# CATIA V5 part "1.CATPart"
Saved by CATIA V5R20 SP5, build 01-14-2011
Part number: 创意
Material "Aluminium": density 2710 kg/m3, Young's modulus 7e+10 Pa, Poisson ratio 0.346, thermal expansion 2.36e-05 1/K
Bounding box of the stored display mesh (mm): x -39 to 39, y -81 to 114.612, z -3.99 to 5.5
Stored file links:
  E:\scc\chuangyi.CATPart
  C:\Program Files\Dassault Systemes\B20\intel_a\startup\materials\Catalog.CATMaterial
  C:\Program Files\Dassault Systemes\B20\intel_a\startup\materials\lead.jpg
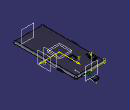
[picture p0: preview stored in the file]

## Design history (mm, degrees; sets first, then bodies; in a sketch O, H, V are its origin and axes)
Body1 (main body), material "Aluminium"
  Sketch1 on xy-plane, origin (0, 0, 0), H (1, 0, 0), V (0, 1, 0)
    line L1 (38.5, 81) -> (38.5, -81)
    line L2 (38.5, -81) -> (-38.5, -81)
    line L3 (-38.5, -81) -> (-38.5, 81)
    line L4 (-38.5, 81) -> (38.5, 81)
    length L4 = 77
    length L1 = 162
    vertical: L1 V, L3 V
    horizontal: L2 H, L4 H
    equidistance: L1 L3 O, L2 L4 O
  Pad1: profile Sketch1, direction (0, 0, 1), length 3.99, mirrored extent
  Fillet1: radius 5, on edge [face of Pad1 from Sketch1.L2 | face of Pad1 from Sketch1.L3]
  Fillet2: radius 5, on edge [face of Pad1 from Sketch1.L1 | face of Pad1 from Sketch1.L2]; edge [face of Pad1 from Sketch1.L4 | face of Pad1 from Sketch1.L1]; edge [face of Pad1 from Sketch1.L3 | face of Pad1 from Sketch1.L4]
  Fillet3: radius 3.99, on edge [face of Pad1 from Sketch1.L3 | end face of Pad1]
  Fillet4: radius 3.99, on edge [start face of Pad1 | face of Pad1 from Sketch1.L3]
  Sketch2 on xy-plane, origin (0, 0, 0), H (1, 0, 0), V (0, 1, 0)
    point P1 (0, 36.3564)
    line L1 (6, 42.3564) -> (6, 30.3564)
    line L2 (6, 30.3564) -> (-6, 30.3564)
    line L3 (-6, 30.3564) -> (-6, 42.3564)
    line L4 (-6, 42.3564) -> (6, 42.3564)
    construction line L5 (-25.3865, 65.2808) -> (-25.3865, 54.4342)
    line L6 (-20.2504, 65.2808) -> (-20.2504, 54.4342)
    line L7 (-30.5227, 54.4342) -> (-30.5227, 65.2808)
    arc A1 centre (-25.3865, 54.4342) radius 5.1361 from (-20.2504, 54.4342) to (-30.5227, 54.4342) cw
    arc A2 centre (-25.3865, 65.2808) radius 5.1361 from (-30.5227, 65.2808) to (-20.2504, 65.2808) cw
    circle A3 centre (-25.3865, 43.9892) radius 1.6328
    point P12 (-25.3865, 43.9892)
    point P13 (-25.3865, 45.6221)
    circle A4 centre (-25.3865, 65.2808) radius 2.0148
    circle A5 centre (-25.3865, 65.2808) radius 3.1825
    circle A6 centre (-25.3865, 54.4342) radius 1.4225
    circle A7 centre (-25.3865, 54.4342) radius 2.9911
    length L1 = 12
    length L2 = 12
    distance L5 L6 = 5.1361
    coincidence: P1 V, P12 L5, A3 P13, P13 L5
    vertical: L1 V, L3 V, L5 V
    horizontal: L2 H, L4 H
    equidistance: L1 L3 P1, L2 L4 P1
    tangency: A1 L6, A2 L6, A1 L7, A2 L7, A3 L4
  Pocket1: profile Sketch2, direction (0, 0, -1), length 1
  Sketch3 on xy-plane, origin (0, 0, 0), H (1, 0, 0), V (0, 1, 0)
    construction line L1 (-25.4108, 65.0293) -> (-25.4108, 53.2602)
    line L2 (-19.9486, 65.0293) -> (-19.9486, 53.2602)
    line L3 (-30.8731, 53.2602) -> (-30.8731, 65.0293)
    arc A1 centre (-25.4108, 53.2602) radius 5.4623 from (-19.9486, 53.2602) to (-30.8731, 53.2602) cw
    arc A2 centre (-25.4108, 65.0293) radius 5.4623 from (-30.8731, 65.0293) to (-19.9486, 65.0293) cw
    circle A3 centre (-25.4108, 65.0293) radius 1.7194
    circle A4 centre (-25.4108, 65.0293) radius 3.6037
    circle A5 centre (-25.4108, 53.2602) radius 1.997
    circle A6 centre (-25.4108, 53.2602) radius 3.278
    distance L1 L2 = 5.4623
    vertical: L1 V
    tangency: A1 L2, A2 L2, A1 L3, A2 L3
  Pad2: profile Sketch3, direction (0, 0, 1), length 1
  Sketch4 on xy-plane, origin (0, 0, 0), H (1, 0, 0), V (0, 1, 0)
    construction line L1 (-24.8106, 64.61) -> (-24.8106, 53.11)
    point P1 (-24.8106, 64.61)
    line L2 (-19.1177, 64.61) -> (-19.1177, 53.11)
    line L3 (-30.5034, 53.11) -> (-30.5034, 64.61)
    arc A1 centre (-24.8106, 53.11) radius 5.6928 from (-19.1177, 53.11) to (-30.5034, 53.11) cw
    arc A2 centre (-24.8106, 64.61) radius 5.6928 from (-30.5034, 64.61) to (-19.1177, 64.61) cw
    reference projected line E1 (-33.5, 77.01) -> (33.5, 77.01) from edge [end face of Pad1 | face of Fillet3]
    distance L1 L2 = 5.6928
    length L2 = 11.5
    distance P1 E1 = 12.4
    vertical: L1 V
    tangency: A1 L2, A2 L2, A1 L3, A2 L3
  Sketch5 on xy-plane, origin (0, 0, 0), H (1, 0, 0), V (0, 1, 0)
    construction line L1 (-24.8106, 64.8298) -> (-24.8106, 53.0607)
    point P1 (-24.8106, 64.8298)
    line L2 (-19.6083, 64.8298) -> (-19.6083, 53.0607)
    line L3 (-30.0128, 53.0607) -> (-30.0128, 64.8298)
    arc A1 centre (-24.8106, 53.0607) radius 5.2023 from (-19.6083, 53.0607) to (-30.0128, 53.0607) cw
    arc A2 centre (-24.8106, 64.8298) radius 5.2023 from (-30.0128, 64.8298) to (-19.6083, 64.8298) cw
    reference projected line E1 (-33.5, 77.01) -> (33.5, 77.01) from edge [end face of Pad1 | face of Fillet3]
    reference projected line E2 (-34.51, -76) -> (-34.51, 76) from edge [end face of Pad1 | face of Fillet3]
    distance L1 L2 = 5.2023
    length L2 = 11.7691
    distance E1 P1 = 12.1802
    distance E2 L3 = 4.4972
    vertical: L1 V
    tangency: A1 L2, A2 L2, A1 L3, A2 L3
  Pad3: profile Sketch4, direction (0, 0, 1), length 1
  Pad4: profile Sketch5, direction (0, 0, 1), length 1
  Sketch6 on xy-plane, origin (0, 0, 0), H (1, 0, 0), V (0, 1, 0)
    construction line L1 (-25.2798, 64.8632) -> (-25.2798, 53.3363)
    point P2 (-25.2798, 53.3363)
    line L2 (-19.9502, 64.8632) -> (-19.9502, 53.3363)
    line L3 (-30.6093, 53.3363) -> (-30.6093, 64.8632)
    arc A1 centre (-25.2798, 53.3363) radius 5.3295 from (-19.9502, 53.3363) to (-30.6093, 53.3363) cw
    arc A2 centre (-25.2798, 64.8632) radius 5.3295 from (-30.6093, 64.8632) to (-19.9502, 64.8632) cw
    distance L1 L2 = 5.3295
    distance H P2 = 53.3363
    length L2 = 11.5269
    vertical: L1 V
    tangency: A1 L2, A2 L2, A1 L3, A2 L3
  Pad5: profile Sketch6, direction (0, 0, 1), length 3
  Sketch7 on xy-plane, origin (0, 0, 0), H (1, 0, 0), V (0, 1, 0)
    construction line L1 (-25.4757, 64.8633) -> (-25.4757, 53.9225)
    point P2 (-25.4757, 53.9225)
    line L2 (-20.3384, 64.8633) -> (-20.3384, 53.9225)
    line L3 (-30.6131, 53.9225) -> (-30.6131, 64.8633)
    arc A1 centre (-25.4757, 53.9225) radius 5.1374 from (-20.3384, 53.9225) to (-30.6131, 53.9225) cw
    arc A2 centre (-25.4757, 64.8633) radius 5.1374 from (-30.6131, 64.8633) to (-20.3384, 64.8633) cw
    distance L1 L2 = 5.1374
    distance P2 H = 53.9225
    length L2 = 10.9408
    vertical: L1 V
    tangency: A1 L2, A2 L2, A1 L3, A2 L3
  Pad6: profile Sketch7, direction (0, 0, 1), length 4.99
  Sketch8 on xy-plane, origin (0, 0, 0), H (1, 0, 0), V (0, 1, 0)
    circle A1 centre (-25.2798, 65.0586) radius 1.4118
    circle A2 centre (-25.2798, 65.0586) radius 2.7436
    circle A3 centre (-25.2798, 54.1178) radius 1.2533
    circle A4 centre (-25.2798, 54.1178) radius 2.9395
    radius A1 = 1.4118
    radius A2 = 2.7436
    radius A3 = 1.2533
    radius A4 = 2.9395
  Pad7: profile Sketch8, direction (0, 0, 1), length 5.5
  Sketch9 on xy-plane, origin (0, 0, 0), H (1, 0, 0), V (0, 1, 0)
    circle A1 centre (-25.3429, 44.3174) radius 1.1965
    circle A2 centre (-25.3429, 44.3174) radius 2.198
    radius A1 = 1.1965
    radius A2 = 2.198
  Pad8: profile Sketch9, direction (0, 0, 1), length 4
  Plane1: type Offset, RefPlane xy-plane, Offset 3.99
  Sketch10 on Plane1, origin (0, 0, 3.99), H (1, 0, 0), V (0, 1, 0)
    point P1 (0, 33.0703)
    line L1 (6, 39.0703) -> (6, 27.0703)
    line L2 (6, 27.0703) -> (-6, 27.0703)
    line L3 (-6, 27.0703) -> (-6, 39.0703)
    line L4 (-6, 39.0703) -> (6, 39.0703)
    length L1 = 12
    length L2 = 12
    coincidence: P1 V
    vertical: L1 V, L3 V
    horizontal: L2 H, L4 H
    equidistance: L1 L3 P1, L2 L4 P1
  Pocket2: profile Sketch10, direction (0, 0, -1), length 1
  Fillet5: radius 0.5, on edge [end face of Pad1 | face of Pocket2 from Sketch10.L4]; edge [end face of Pad1 | face of Pocket2 from Sketch10.L1]
  Fillet6: radius 0.5, on edge [end face of Pad1 | face of Pocket2 from Sketch10.L2]
  Fillet7: radius 0.5, on edge [end face of Pad1 | face of Pocket2 from Sketch10.L3]
  Fillet8: radius 0.5, on edge [face of Fillet5 | face of Fillet7]
  Sketch11 on zx-plane, origin (0, 0, 0), H (-1, 0, 0), V (0, 0, 1)
    point P1 (-21.6197, 0)
    line L1 (-16.608, 1.3345) -> (-16.608, -1.3345)
    line L2 (-16.608, -1.3345) -> (-26.6314, -1.3345)
    line L3 (-26.6314, -1.3345) -> (-26.6314, 1.3345)
    line L4 (-26.6314, 1.3345) -> (-16.608, 1.3345)
    length L4 = 10.0234
    length L1 = 2.669
    coincidence: P1 H
    vertical: L1 V, L3 V
    horizontal: L2 H, L4 H
    equidistance: L1 L3 P1, L2 L4 P1
  Pad9: profile Sketch11, direction (0, 1, 0), length 1
  Plane2: type Offset, RefPlane zx-plane, Offset 81
  Sketch12 on Plane2, origin (0, 81, 0), H (-1, 0, 0), V (0, 0, 1)
    circle A1 centre (7.2071, 0) radius 0.3459
    point P1 (7.2071, 0)
    point P2 (7.5531, 0)
    circle A2 centre (15.1062, 0) radius 1.1562
    point P3 (15.1062, 0)
    coincidence: P1 H, A1 P2, P2 H, P3 H
  Pocket3: profile Sketch12, direction (0, -1, 0), length 5
  Plane3: type Offset, RefPlane yz-plane, Offset 38.5
  Sketch13 on Plane3, origin (38.5, 0, 0), H (0, 1, 0), V (0, 0, 1)
    construction line L1 (31.5997, 0) -> (47.6279, 0)
    point P1 (31.5997, 0)
    point P2 (47.6279, 0)
    line L2 (31.5997, 1.8741) -> (47.6279, 1.8741)
    line L3 (47.6279, -1.8741) -> (31.5997, -1.8741)
    arc A1 centre (47.6279, 0) radius 1.8741 from (47.6279, 1.8741) to (47.6279, -1.8741) cw
    arc A2 centre (31.5997, 0) radius 1.8741 from (31.5997, -1.8741) to (31.5997, 1.8741) cw
    reference intersected line E1 through (81, 0) direction (0, 1) from Plane2
    distance L1 L2 = 1.8741
    length L3 = 16.0282
    distance P2 E1 = 33.3721
    coincidence: P1 H
    horizontal: L1 H
    tangency: A1 L2, A2 L2, A1 L3, A2 L3
  Pad10: profile Sketch13, direction (1, 0, 0), length 0.5
  Sketch14 on Plane3, origin (38.5, 0, 0), H (0, 1, 0), V (0, 0, 1)
    point P1 (11.3902, 0)
    line L1 (18.359, 1.3919) -> (18.359, -1.3919)
    line L2 (18.359, -1.3919) -> (4.4214, -1.3919)
    line L3 (4.4214, -1.3919) -> (4.4214, 1.3919)
    line L4 (4.4214, 1.3919) -> (18.359, 1.3919)
    length L2 = 13.9376
    coincidence: P1 H
    vertical: L1 V, L3 V
    horizontal: L2 H, L4 H
    equidistance: L1 L3 P1, L2 L4 P1
  Pad11: profile Sketch14, direction (1, 0, 0), length 0.5
  Sketch15 on yz-plane, origin (0, 0, 0), H (0, 1, 0), V (0, 0, 1)
    line L1 (8.1368, 1.5106) -> (8.1368, -1.5106)
    line L2 (8.1368, -1.5106) -> (-8.1368, -1.5106)
    line L3 (-8.1368, -1.5106) -> (-8.1368, 1.5106)
    line L4 (-8.1368, 1.5106) -> (8.1368, 1.5106)
    length L2 = 16.2737
    vertical: L1 V, L3 V
    horizontal: L2 H, L4 H
    equidistance: L1 L3 O, L2 L4 O
  Pad12: profile Sketch15, direction (-1, 0, 0), length 39
  Plane4: type Offset, RefPlane zx-plane, Offset 81, reversed
  Sketch16 on Plane4, origin (0, -81, 0), H (-1, 0, 0), V (0, 0, 1)
    line L1 (6.1055, 0.942) -> (6.1055, -0.942)
    line L2 (6.1055, -0.942) -> (-6.1055, -0.942)
    line L3 (-6.1055, -0.942) -> (-6.1055, 0.942)
    line L4 (-6.1055, 0.942) -> (6.1055, 0.942)
    vertical: L1 V, L3 V
    horizontal: L2 H, L4 H
    equidistance: L1 L3 O, L2 L4 O
  Pocket4: profile Sketch16, direction (0, 1, 0), length 5
  Sketch17 on Plane2, origin (0, 81, 0), H (-1, 0, 0), V (0, 0, 1)
    point P1 (-20, 0)
    line L1 (-15, 1.75) -> (-15, -1.75)
    line L2 (-15, -1.75) -> (-25, -1.75)
    line L3 (-25, -1.75) -> (-25, 1.75)
    line L4 (-25, 1.75) -> (-15, 1.75)
    length L2 = 10
    length L1 = 3.5
    coincidence: P1 H
    vertical: L1 V, L3 V
    horizontal: L2 H, L4 H
    equidistance: L1 L3 P1, L2 L4 P1
  Pocket5: profile Sketch17, direction (0, -1, 0), length 10
  Sketch18 on Plane2, origin (0, 81, 0), H (-1, 0, 0), V (0, 0, 1)
    reference intersected line E1 through (-38.5, 0) direction (0, -1) from Plane3
    reference projected point E2 (-25, 0) from vertex [face of Fillet3 | face of Pocket5 from Sketch17.L3 | face of Fillet4]
    distance E1 E2 = 13.5 (reference)
  Plane5: type Offset, RefPlane Plane3, Offset 14.5, reversed
  Sketch19 on xy-plane, origin (0, 0, 0), H (1, 0, 0), V (0, 1, 0)
    point P1 (14.0539, 104.669)
    line L1 (19.0539, 109.669) -> (19.0539, 99.669)
    line L2 (19.0539, 99.669) -> (9.0539, 99.669)
    line L3 (9.0539, 99.669) -> (9.0539, 109.669)
    line L4 (9.0539, 109.669) -> (19.0539, 109.669)
    length L2 = 10
    length L1 = 10
    vertical: L1 V, L3 V
    horizontal: L2 H, L4 H
    equidistance: L1 L3 P1, L2 L4 P1
  Pad13: profile Sketch19, direction (0, 0, 1), length 3.5
  Sketch20 on start face of Pad13, origin (0, 0, 0), H (1, 0, 0), V (0, -1, 0)
    circle A1 centre (14.1454, -104.504) radius 1.8002
    circle A2 centre (14.1454, -104.504) radius 3.4786
  Pocket6: profile Sketch20, direction (0, 0, 1), length 0.5
  Sketch21 on xy-plane, origin (0, 0, 0), H (1, 0, 0), V (0, 1, 0)
    axis line L1 (19.9716, 59.9572) -> (19.9716, 114.6121)
    vertical: L1 V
